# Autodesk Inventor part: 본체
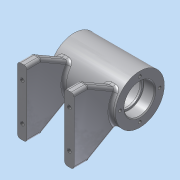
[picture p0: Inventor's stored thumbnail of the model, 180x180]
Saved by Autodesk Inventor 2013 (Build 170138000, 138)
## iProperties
Created: 2018-05
Part Number: 본체
Material: 알루미늄 6061
Document SubType Name: Modeling
Designer: dgall
Density: 2.71 g/cm^3
Mass: 319.021 g
Surface Area: 375.652 cm^2
Volume: 117.72 cm^3
Author: dgall
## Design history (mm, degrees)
sketch "스케치1"
  geometry: L1 (0, 0)-(70, 0); L2 (0, 16)-(0, 26); L3 (0, 26)-(70, 26); L4 (70, 26)-(70, 16); L5 (0, 16)-(12, 16); L6 (12, 16)-(12, 14); L7 (12, 14)-(14, 14); L8 (14, 14)-(14, 21); L9 (14, 21)-(56, 21); L10 (56, 21)-(56, 14); L11 (56, 14)-(58, 14); L12 (58, 14)-(58, 16); L13 (58, 16)-(70, 16)
  constraints: 26 end point, 6 perpendicular, 4 parallel, 2 collinear, 2 horizontal, 2 horizontal alignment, 2 vertical alignment, 1 vertical
  dimensions: "d0" = 70 distance of L1.start L1.end; "d1" = 52 diameter of L3 L1; "d2" = 12 distance of L2.start L5.end; "d3" = 42 distance of L8.end L9.end; "d4" = 32 diameter of L5 L1; "d5" = 28 diameter of L7 L1; "d6" = 42 diameter of L9 L1
revolve "회전1" sketch "스케치1" stored, may be unused: angle "d7" = 90 deg
sketch "스케치2"
  geometry: C1 r 26 at (0, 0) reference; 1 further point
  constraints: 1 vertical alignment
  dimensions: "d8" = 21 distance of C1.centre point (0, 21)
hole "구멍1" sketch "스케치2" at (0, 21) diameter "d9" = 3.242; stored, may be unused: countersink angle "d13" = 90 deg, drill point angle "d15" = 118 deg; dims "d10" = 8, "d11" = 4, "d12" = 2, "d14" = 10
node "작업 평면1"
node "작업 평면3"
  node "작업 평면2"
sketch "스케치3"
  geometry: L1 (0, 26)-(0, -26) reference; C1 r 5 at (-35, 0); 2 further points
  constraints: 1 centre point, 1 horizontal alignment, 1 midpoint
  dimensions: "d20" = 35 distance from line of L1 C1.centre; "d21" = 10 diameter of C1
extrude "돌출1" join sketch "스케치3" stored distance "d22" = 10; taper "d23" = 0 deg
sketch "스케치4"
  geometry: C1 r 5 at (0, 0) reference; 2 further points
  constraints: 1 coincident
hole "구멍2" sketch "스케치4" at (0, 0) diameter "d25" = 5.188; stored, may be unused: countersink angle "d29" = 90 deg, drill point angle "d31" = 118 deg; dims "d26" = 8, "d27" = 4, "d28" = 2, "d30" = 10
node "작업 평면5"
  node "작업 평면4"
sketch "스케치5"
  geometry: L1 (-17.325, -19.386)-(-35, -50); L2 (-35, -50)-(-35, -65); L3 (-35, -65)-(35, -65); L4 (35, -65)-(35, -50); L5 (35, -50)-(17.325, -19.386); C1 r 1.621 at (-21, 0) reference; C2 r 1.621 at (0, -21) reference; C3 r 1.621 at (21, 0) reference; C4 r 1.621 at (0, 21) reference; C5 r 16 at (0, 0) reference; A1 r 26 centre (0, 0) between (-17.325, -19.386) and (17.325, -19.386) reference; 2 further points
  constraints: 10 end point, 2 perpendicular, 2 point on circle, 1 equal length, 1 midpoint, 1 vertical, 1 vertical alignment
  dimensions: "d33" = 30 deg angle of L5 L4; "d34" = 70 distance of L2.end L3.end; "d36" = 15 distance of L3.end L4.end; "d37" = 65 distance from line of point (0, 0) L3; "d38" = 30 deg angle of L1 L2
extrude "돌출2" join sketch "스케치5" distance "d39" = 10; taper "d40" = 0 deg
sketch "스케치6"
  geometry: L1 (0, 0)-(0, -43.641); L2 (0, 0)-(0, -43.641); L3 (0, 0)-(-9.919, -27.251); C1 r 1.621 at (-21, 0) reference; C2 r 1.621 at (0, -21) reference; C3 r 1.621 at (21, 0) reference; C4 r 1.621 at (0, 21) reference; C5 r 26 at (0, 0) reference; C6 r 16 at (0, 0) reference; 1 further point
  constraints: 6 end point, 1 collinear, 1 vertical
  dimensions: "d80" = 20 deg angle of L1 L3; "d81" = 29 distance of L1.start L3.end
  node "투영된 루프2"
node "작업 평면12"
sketch "스케치12"
  geometry: C1 r 6 at (0, 0); 2 further points
  constraints: 1 centre point, 1 coincident
  dimensions: "d82" = 12 diameter of C1
extrude "돌출4" join sketch "스케치12" stored distance "d84" = 10; taper "d85" = 0 deg
sketch "스케치13"
  geometry: C1 r 6 at (0, 0) reference; 2 further points
  constraints: 1 coincident
hole "구멍5" sketch "스케치13" at (0, 0) diameter "d86" = 5.188; stored, may be unused: countersink angle "d90" = 90 deg, drill point angle "d92" = 118 deg; dims "d87" = 8, "d88" = 4, "d89" = 2, "d91" = 10
fillet "모깎기7" dims "d93" = 2
sketch "스케치9"
  geometry: L1 (0, 70)-(-10, 70) reference; 4 further points
  constraints: 2 vertical alignment, 1 midpoint
  dimensions: "d54" = 20 vertical distance of point (-15, 35) point (-5, 55); "d55" = 20 vertical distance of point (-15, 35) point (-5, 15)
hole "구멍4" sketch "스케치9" at (-5, 55), (-5, 15) diameter "d56" = 4.134; stored, may be unused: countersink angle "d60" = 90 deg, drill point angle "d62" = 118 deg; dims "d57" = 8, "d58" = 4, "d59" = 2, "d61" = 10
node "작업 평면7"
chamfer "모따기1" distance "d63" = 1; stored, may be unused: second distance "d64" = 2, angle "d65" = 45 deg
fillet "모깎기1" dims "d66" = 3
fillet "모깎기2" dims "d67" = 0.3
fillet "모깎기3" dims "d68" = 2
fillet "모깎기5" dims "d70" = 3
fillet "모깎기6" dims "d71" = 3
node "작업 평면11"
  node "작업 평면10"
sketch "스케치11"
  geometry: L1 (0, 26)-(-70, 26) reference; 2 further points
  constraints: 1 horizontal alignment, 1 other
  dimensions: "d77" = 35 distance of point (0, 0) point (-35, 0)
feature "엠보싱2" sketch "스케치11" dims "d0" = 70, "d1" = 52, "d2" = 12, "d3" = 42, "d4" = 32, "d5" = 28, "d6" = 42, "d78" = 0.5, "d79" = 0
node "솔리드1"
pattern_circular "원형 패턴1" dims angle "d17" = 360 deg
mirror "대칭1"
mirror "대칭2"
mirror "대칭3"
node "투영된 루프1"
other parameters: "d24" = 29, "d76" = 62.75
